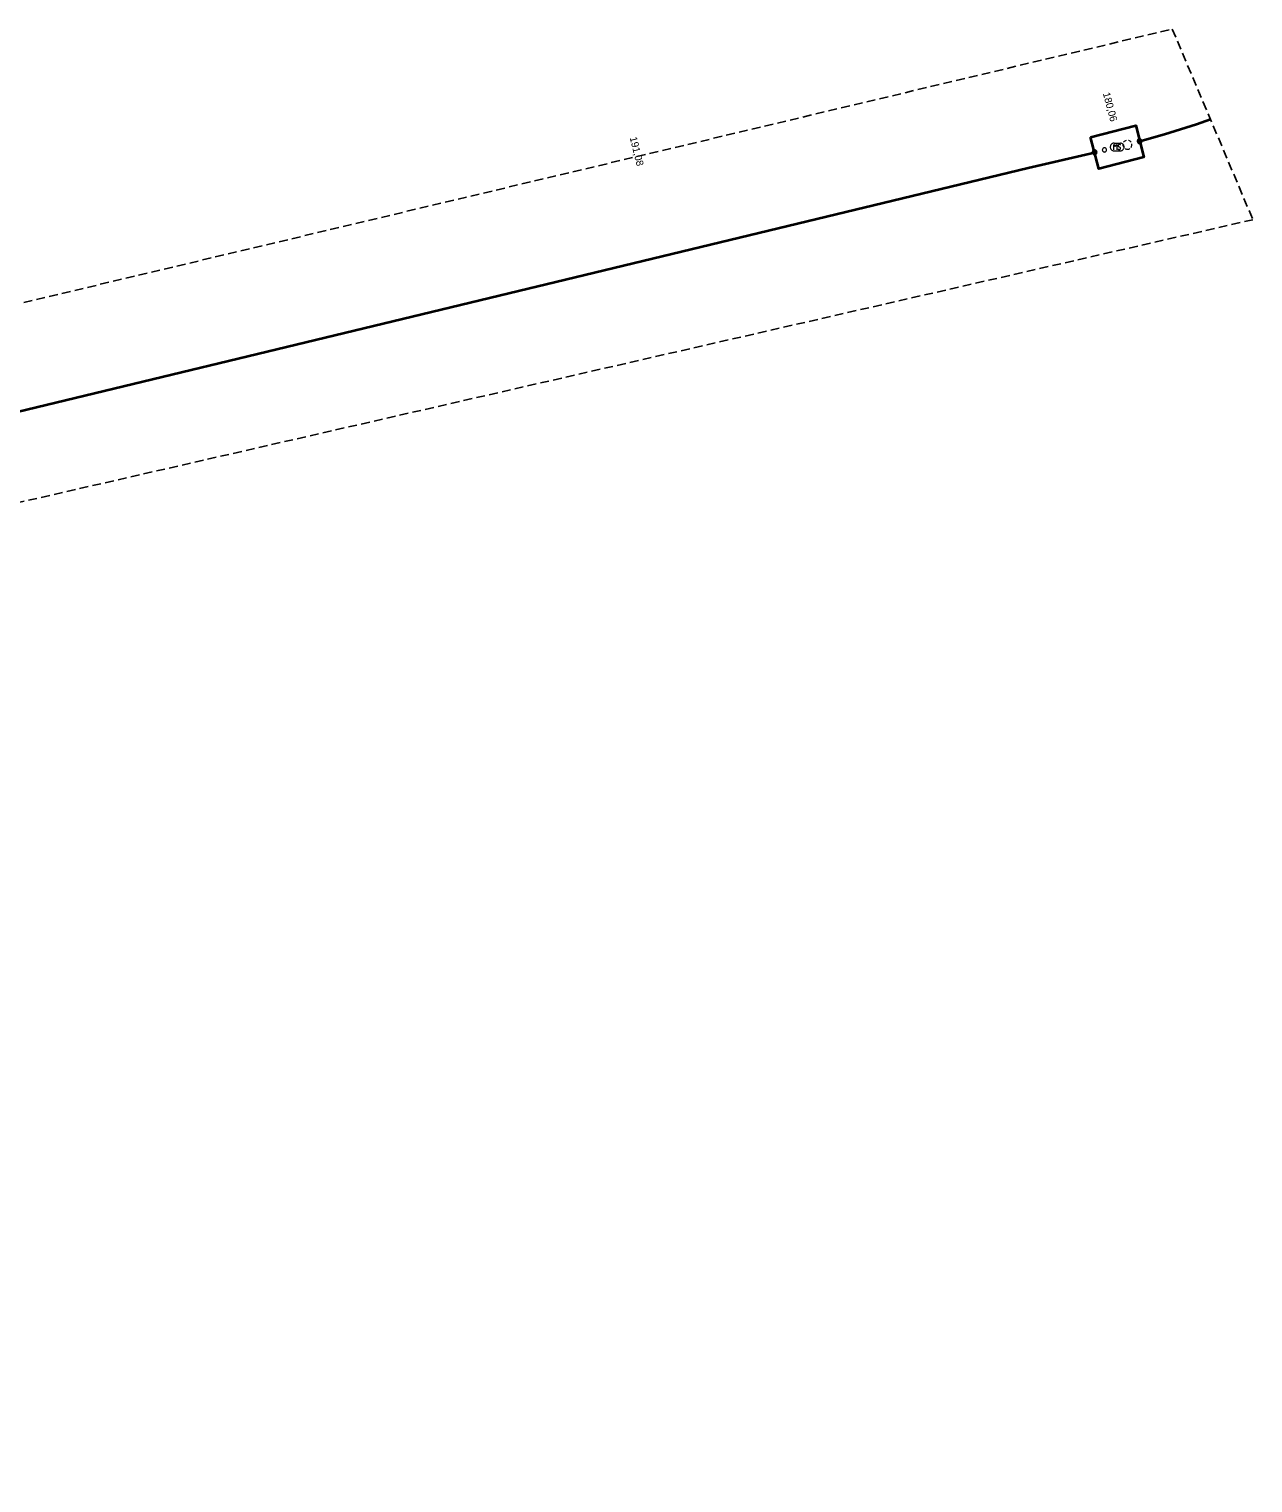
# Model space of a CAD drawing. Extents: x -744446 to -743929, y -1041261 to -1040599.
# Drawn here: x -744062.9 to -743928.7, y -1040758 to -1040598.6 of the extents above; entities that cross this region are included whole.
import ezdxf

# ---------------------------------------------------------------- set-up
doc = ezdxf.new("R2010")
doc.units = 0
doc.header["$LTSCALE"] = 0.32
doc.linetypes.add('LONG_DASHED', pattern=[7.5, 6, -1.5])
doc.linetypes.add('MEDIUM_DASHED', pattern=[4.5, 3, -1.5])
for name, color, linetype, lineweight in [('1', 7, 'MEDIUM_DASHED', 25), ('18', 7, 'Continuous', 13), ('20', 7, 'LONG_DASHED', 13)]:
    doc.layers.add(name, color=color, linetype=linetype, lineweight=lineweight)

msp = doc.modelspace()

# ---------------------------------------------------------------- linework, layer by layer
at = {"layer": '1'}
msp.add_lwpolyline([(-744438.077, -1041259.731), (-744438.679, -1041250.888), (-744445.125, -1041198.426), (-744434.434, -1041080.103), (-744426.87, -1040938.41), (-744425.446, -1040859.072), (-744414.192, -1040822.094), (-744390.076, -1040771.45), (-744357.118, -1040726.434), (-744307.278, -1040693.475), (-744241.36, -1040670.967), (-743937.498, -1040598.618), (-743928.655, -1040619.519), (-744129.684, -1040665.585), (-744218.109, -1040687.29), (-744311.358, -1040718.641), (-744361.198, -1040777.323), (-744391.745, -1040864.141), (-744411.355, -1041059.185), (-744416.379, -1041145.154), (-744432.569, -1041193.163), (-744432.047, -1041202.053), (-744422.803, -1041230.992), (-744424.813, -1041260.936)], close=True, dxfattribs=at)
at = {"layer": '18'}
for p, q in [((-743943.916, -1040611.844), (-743943.916, -1040611.269)), ((-743943.87, -1040611.124), (-743943.163, -1040611.124)), ((-743943.591, -1040611.267), (-743943.591, -1040611.841)), ((-743943.908, -1040611.977), (-743943.187, -1040611.977))]:
    msp.add_line(p, q, dxfattribs=at)
at = {"layer": '18', "lineweight": 35}
msp.add_lwpolyline([(-743946.46, -1040610.469), (-743941.511, -1040609.178), (-743940.602, -1040612.663), (-743945.544, -1040613.952), (-743946.458, -1040610.476)], close=True, dxfattribs=at)
at = {"layer": '18'}
for points in [[(-743944.716, -1040611.816), (-743944.734, -1040611.767), (-743944.762, -1040611.722), (-743944.8, -1040611.685), (-743944.845, -1040611.658), (-743944.895, -1040611.642), (-743944.947, -1040611.638), (-743944.999, -1040611.645), (-743945.048, -1040611.663), (-743945.092, -1040611.693), (-743945.128, -1040611.732), (-743945.153, -1040611.778), (-743945.168, -1040611.828), (-743945.171, -1040611.881), (-743945.162, -1040611.932), (-743945.143, -1040611.981), (-743945.111, -1040612.023), (-743945.072, -1040612.058), (-743945.025, -1040612.083), (-743944.975, -1040612.096), (-743944.922, -1040612.098), (-743944.871, -1040612.088), (-743944.823, -1040612.067), (-743944.781, -1040612.034), (-743944.747, -1040611.994), (-743944.724, -1040611.947), (-743944.712, -1040611.896), (-743944.712, -1040611.844)], [(-743940.81, -1040610.913), (-743940.816, -1040610.857), (-743940.833, -1040610.804), (-743940.862, -1040610.755), (-743940.9, -1040610.714), (-743940.946, -1040610.682), (-743940.998, -1040610.66), (-743941.053, -1040610.649), (-743941.109, -1040610.651), (-743941.164, -1040610.664), (-743941.215, -1040610.689), (-743941.259, -1040610.724), (-743941.295, -1040610.767), (-743941.32, -1040610.817), (-743941.335, -1040610.872), (-743941.338, -1040610.928), (-743941.329, -1040610.983), (-743941.308, -1040611.036), (-743941.277, -1040611.082), (-743941.237, -1040611.121), (-743941.189, -1040611.151), (-743941.136, -1040611.17), (-743941.08, -1040611.177), (-743941.024, -1040611.173), (-743940.97, -1040611.156), (-743940.921, -1040611.129), (-743940.879, -1040611.091), (-743940.846, -1040611.046), (-743940.823, -1040610.995), (-743940.811, -1040610.94)], [(-743940.869, -1040610.916), (-743940.875, -1040610.867), (-743940.893, -1040610.821), (-743940.921, -1040610.78), (-743940.958, -1040610.747), (-743941.002, -1040610.725), (-743941.05, -1040610.713), (-743941.099, -1040610.713), (-743941.147, -1040610.725), (-743941.191, -1040610.748), (-743941.228, -1040610.781), (-743941.256, -1040610.822), (-743941.273, -1040610.869), (-743941.279, -1040610.918), (-743941.272, -1040610.967), (-743941.254, -1040611.013), (-743941.226, -1040611.053), (-743941.189, -1040611.086), (-743941.145, -1040611.108), (-743941.096, -1040611.12), (-743941.047, -1040611.119), (-743940.999, -1040611.107), (-743940.956, -1040611.083), (-743940.919, -1040611.05), (-743940.891, -1040611.009), (-743940.875, -1040610.962)], [(-743940.928, -1040610.92), (-743940.934, -1040610.878), (-743940.951, -1040610.84), (-743940.979, -1040610.809), (-743941.014, -1040610.786), (-743941.054, -1040610.775), (-743941.096, -1040610.775), (-743941.136, -1040610.787), (-743941.171, -1040610.81), (-743941.198, -1040610.842), (-743941.215, -1040610.88), (-743941.22, -1040610.921), (-743941.214, -1040610.963), (-743941.196, -1040611), (-743941.168, -1040611.032), (-743941.132, -1040611.054), (-743941.092, -1040611.065), (-743941.05, -1040611.064), (-743941.01, -1040611.051), (-743940.976, -1040611.028), (-743940.949, -1040610.995), (-743940.933, -1040610.957)], [(-743945.753, -1040612.128), (-743945.759, -1040612.072), (-743945.776, -1040612.019), (-743945.804, -1040611.97), (-743945.843, -1040611.929), (-743945.889, -1040611.897), (-743945.941, -1040611.875), (-743945.996, -1040611.864), (-743946.052, -1040611.866), (-743946.107, -1040611.879), (-743946.157, -1040611.904), (-743946.202, -1040611.939), (-743946.238, -1040611.982), (-743946.263, -1040612.032), (-743946.278, -1040612.087), (-743946.281, -1040612.143), (-743946.272, -1040612.198), (-743946.251, -1040612.251), (-743946.22, -1040612.297), (-743946.179, -1040612.336), (-743946.132, -1040612.366), (-743946.079, -1040612.385), (-743946.023, -1040612.392), (-743945.967, -1040612.388), (-743945.913, -1040612.371), (-743945.864, -1040612.344), (-743945.822, -1040612.306), (-743945.789, -1040612.261), (-743945.766, -1040612.21), (-743945.754, -1040612.155)], [(-743945.812, -1040612.131), (-743945.818, -1040612.082), (-743945.836, -1040612.036), (-743945.864, -1040611.995), (-743945.901, -1040611.962), (-743945.945, -1040611.94), (-743945.993, -1040611.928), (-743946.042, -1040611.928), (-743946.09, -1040611.94), (-743946.134, -1040611.963), (-743946.171, -1040611.996), (-743946.199, -1040612.037), (-743946.216, -1040612.084), (-743946.222, -1040612.133), (-743946.215, -1040612.182), (-743946.197, -1040612.228), (-743946.169, -1040612.268), (-743946.132, -1040612.301), (-743946.088, -1040612.323), (-743946.039, -1040612.335), (-743945.99, -1040612.334), (-743945.942, -1040612.322), (-743945.899, -1040612.298), (-743945.862, -1040612.265), (-743945.834, -1040612.224), (-743945.818, -1040612.177)], [(-743945.871, -1040612.135), (-743945.877, -1040612.093), (-743945.894, -1040612.055), (-743945.922, -1040612.024), (-743945.956, -1040612.001), (-743945.997, -1040611.99), (-743946.039, -1040611.99), (-743946.079, -1040612.002), (-743946.114, -1040612.025), (-743946.141, -1040612.057), (-743946.157, -1040612.095), (-743946.163, -1040612.136), (-743946.157, -1040612.178), (-743946.139, -1040612.215), (-743946.111, -1040612.247), (-743946.075, -1040612.269), (-743946.035, -1040612.28), (-743945.993, -1040612.279), (-743945.953, -1040612.266), (-743945.919, -1040612.243), (-743945.892, -1040612.21), (-743945.876, -1040612.172)]]:
    msp.add_lwpolyline(points, close=True, dxfattribs=at)
for points in [[(-743943.862, -1040611.124), (-743943.933, -1040611.129), (-743944.003, -1040611.146), (-743944.069, -1040611.174), (-743944.129, -1040611.213), (-743944.182, -1040611.261), (-743944.226, -1040611.317), (-743944.26, -1040611.38), (-743944.283, -1040611.448), (-743944.294, -1040611.519), (-743944.294, -1040611.591), (-743944.281, -1040611.661), (-743944.257, -1040611.729), (-743944.222, -1040611.791), (-743944.177, -1040611.847), (-743944.124, -1040611.894), (-743944.063, -1040611.932), (-743943.997, -1040611.96), (-743943.927, -1040611.975), (-743943.908, -1040611.978)], [(-743943.916, -1040611.269), (-743943.749, -1040611.508), (-743943.591, -1040611.267)], [(-743943.447, -1040611.757), (-743943.423, -1040611.792), (-743943.392, -1040611.818), (-743943.353, -1040611.835), (-743943.312, -1040611.84), (-743943.271, -1040611.833), (-743943.234, -1040611.815), (-743943.203, -1040611.786), (-743943.182, -1040611.751), (-743943.172, -1040611.71), (-743943.174, -1040611.669), (-743943.187, -1040611.629), (-743943.211, -1040611.596), (-743943.244, -1040611.57), (-743943.282, -1040611.555), (-743943.304, -1040611.551)], [(-743943.161, -1040611.354), (-743943.182, -1040611.318), (-743943.212, -1040611.29), (-743943.249, -1040611.272), (-743943.29, -1040611.265), (-743943.331, -1040611.27), (-743943.369, -1040611.287), (-743943.401, -1040611.313), (-743943.423, -1040611.348), (-743943.435, -1040611.388), (-743943.435, -1040611.429), (-743943.423, -1040611.469), (-743943.4, -1040611.503), (-743943.369, -1040611.53), (-743943.331, -1040611.546), (-743943.303, -1040611.551)], [(-743943.188, -1040611.977), (-743943.117, -1040611.969), (-743943.048, -1040611.949), (-743942.984, -1040611.917), (-743942.925, -1040611.875), (-743942.875, -1040611.825), (-743942.834, -1040611.766), (-743942.803, -1040611.702), (-743942.783, -1040611.633), (-743942.775, -1040611.562), (-743942.779, -1040611.49), (-743942.795, -1040611.42), (-743942.822, -1040611.354), (-743942.86, -1040611.293), (-743942.908, -1040611.24), (-743942.964, -1040611.195), (-743943.026, -1040611.16), (-743943.094, -1040611.136), (-743943.163, -1040611.124)], [(-743942.908, -1040611.219), (-743942.914, -1040611.296), (-743942.909, -1040611.373), (-743942.892, -1040611.448), (-743942.863, -1040611.519), (-743942.823, -1040611.585), (-743942.807, -1040611.607)], [(-743942.563, -1040610.827), (-743942.634, -1040610.855), (-743942.701, -1040610.894), (-743942.761, -1040610.942), (-743942.812, -1040610.999), (-743942.836, -1040611.033)], [(-743942.022, -1040611.01), (-743942.072, -1040610.952), (-743942.13, -1040610.902), (-743942.195, -1040610.861), (-743942.266, -1040610.832), (-743942.315, -1040610.818)], [(-743942.027, -1040611.596), (-743941.986, -1040611.531), (-743941.955, -1040611.461), (-743941.936, -1040611.386), (-743941.928, -1040611.31), (-743941.933, -1040611.233), (-743941.939, -1040611.198)], [(-743942.65, -1040611.736), (-743942.58, -1040611.767), (-743942.505, -1040611.786), (-743942.429, -1040611.793), (-743942.352, -1040611.788), (-743942.277, -1040611.771), (-743942.205, -1040611.743), (-743942.145, -1040611.708)]]:
    msp.add_lwpolyline(points, dxfattribs=at)
at = {"layer": '20', "linetype": 'Continuous', "lineweight": 35}
for points in [[(-743941.074, -1040610.926), (-743938.348, -1040610.157), (-743934.838, -1040609.045), (-743933.315, -1040608.504)], [(-744429.62, -1041252.21), (-744428.789, -1041237.94), (-744437.959, -1041195.193), (-744423.3, -1041145.69), (-744417.879, -1041053.98), (-744409.949, -1040917.67), (-744407.76, -1040880.01), (-744407.219, -1040869.23), (-744404.395, -1040847.829), (-744400.25, -1040827.35), (-744393.491, -1040807.621), (-744384.879, -1040787.9), (-744372.238, -1040768.547), (-744361.26, -1040752.62), (-744345.317, -1040736.555), (-744330.739, -1040723.14), (-744312.333, -1040710.859), (-744294.67, -1040700.75), (-744274.728, -1040692.583), (-744254.699, -1040686.49), (-744133.87, -1040657.39), (-743953.289, -1040613.85), (-743946.017, -1040612.141)]]:
    msp.add_lwpolyline(points, dxfattribs=at)

# ---------------------------------------------------------------- texts
at = {"layer": '1'}
for s, rotation, p in [('180,06', 285, (-743945.12, -1040605.669)), ('191,08', 284, (-743997, -1040610.524))]:
    msp.add_text(s, height=0.8, rotation=rotation, dxfattribs=at).set_placement(p)

doc.saveas('drawing.dxf')
